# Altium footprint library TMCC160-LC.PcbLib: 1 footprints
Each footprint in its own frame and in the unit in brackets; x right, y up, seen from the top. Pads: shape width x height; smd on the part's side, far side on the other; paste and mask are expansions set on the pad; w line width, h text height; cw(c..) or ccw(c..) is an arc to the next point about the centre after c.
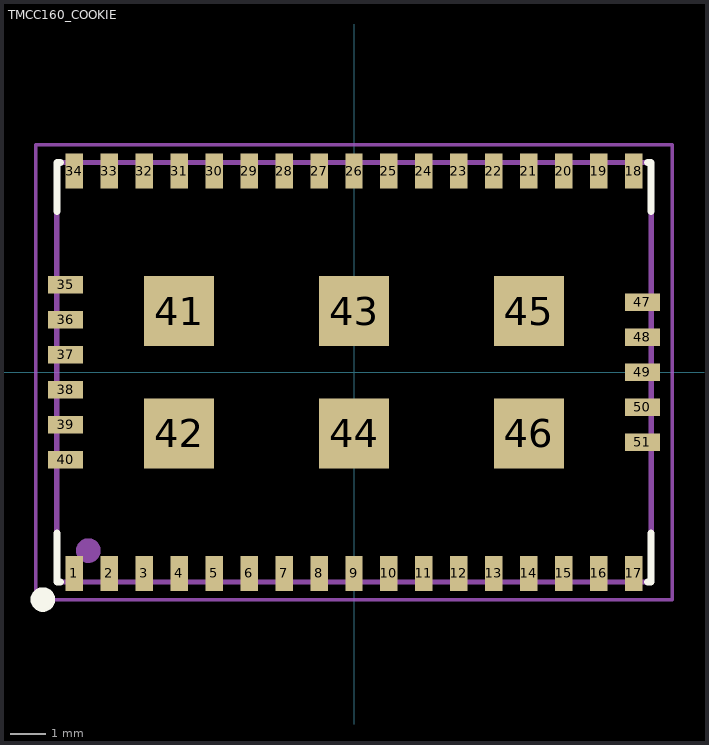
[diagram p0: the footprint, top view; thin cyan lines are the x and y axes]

## TMCC160_COOKIE [mm]
pads (51):
  rect 0.5x1 smd: 1(-8,-5.75) 2(-7,-5.75) 3(-6,-5.75) 4(-5,-5.75) 5(-4,-5.75) 6(-3,-5.75) 7(-2,-5.75) 8(-1,-5.75) 9(0,-5.75) 10(1,-5.75) 11(2,-5.75) 12(3,-5.75) 13(4,-5.75) 14(5,-5.75) 15(6,-5.75) 16(7,-5.75) 17(8,-5.75) 18(8,5.75) 19(7,5.75) 20(6,5.75) 21(5,5.75) 22(4,5.75) 23(3,5.75) 24(2,5.75) 25(1,5.75) 26(0,5.75) 27(-1,5.75) 28(-2,5.75) 29(-3,5.75) 30(-4,5.75) 31(-5,5.75) 32(-6,5.75) 33(-7,5.75) 34(-8,5.75)
  rect 1x0.5 smd: 35(-8.25,2.5) 36(-8.25,1.5) 37(-8.25,0.5) 38(-8.25,-0.5) 39(-8.25,-1.5) 40(-8.25,-2.5) 47(8.25,2) 48(8.25,1) 49(8.25,0) 50(8.25,-1) 51(8.25,-2)
  rect 2x2 smd paste-0.2: 41(-5,1.75) 42(-5,-1.75) 43(0,1.75) 44(0,-1.75) 45(5,1.75) 46(5,-1.75)
L26-Silk Screen Top (Multiple PADS layers...):
  circle w0.5: c-8.9,-6.5 r0.1
  lines w0.2: -8.5,-4.6 -8.5,-6 -8.4,-6 ; -8.5,4.6 -8.5,6 -8.4,6 ; 8.4,-6 8.5,-6 8.5,-4.6 ; 8.4,6 8.5,6 8.5,4.6
L13:
  circle w0.5: c-7.6,-5.1 r0.1
  lines w0.15: -8.5,-6 8.5,-6 8.5,6 -8.5,6 -8.5,-6
L15 (Multiple PADS layers...):
  lines w0.1: -9.1,-6.5 9.1,-6.5 9.1,6.5 -9.1,6.5 -9.1,-6.5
